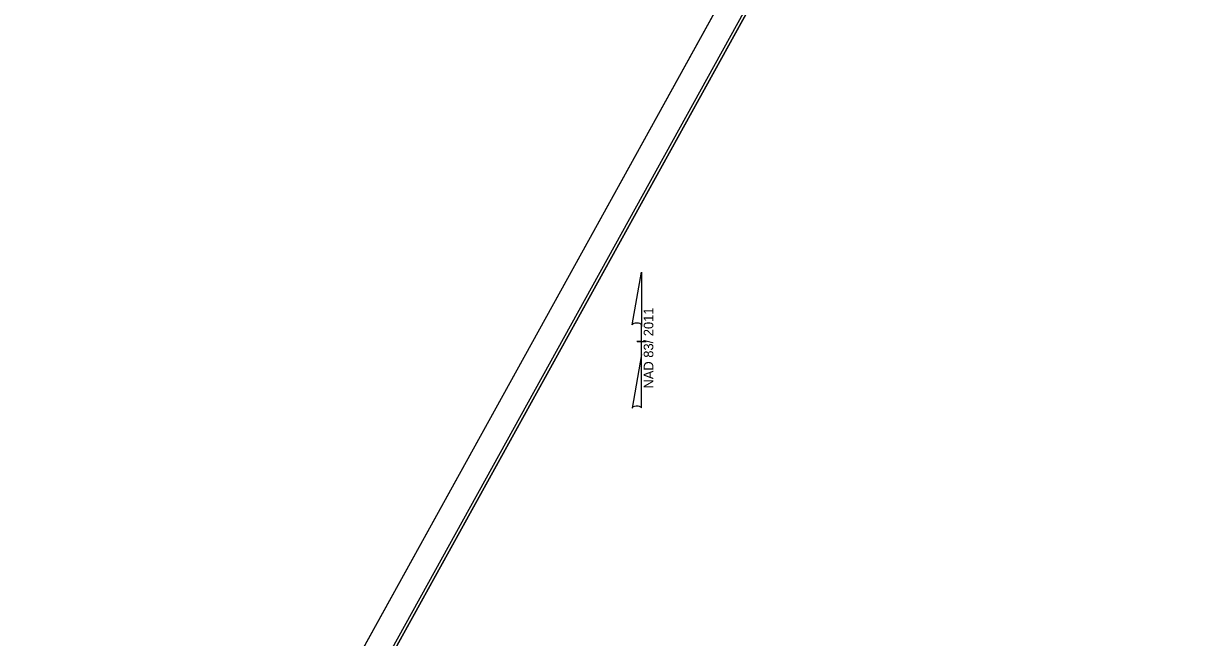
# Model space of a CAD drawing. Extents: x 2176096 to 2177873, y 76962 to 79129.
# Drawn here: x 2176096 to 2177127, y 78046 to 78587 of the extents above; entities that cross this region are included whole.
import ezdxf

# ---------------------------------------------------------------- set-up
doc = ezdxf.new("R2010")
doc.units = 0
for name, color, linetype in [('CTL Primary Horizontal and Vertical CELL', 7, 'Continuous'), ('CTL Primary Horizontal CELL', 7, 'Continuous'), ('CTL Primary Horizontal Cogo Elevation', 7, 'Continuous'), ('CTL Primary Horizontal Cogo Number', 7, 'Continuous'), ('Exist Other Culture Sign Cogo Point CELL', 7, 'Continuous'), ('Exist Property Iron Pin Cogo Comment', 7, 'Continuous')]:
    doc.layers.add(name, color=color, linetype=linetype)

msp = doc.modelspace()

# ---------------------------------------------------------------- linework, layer by layer
at = {"layer": 'CTL Primary Horizontal and Vertical CELL'}
msp.add_lwpolyline([(2176762, 78648.7), (2176276.9, 77771), (2176400.5, 77667.3), (2176500.7, 77583.3), (2176559.2, 77534.4), (2176927.7, 77225.4), (2177117.2, 77120.7), (2177568.3, 77937), (2177830.4, 78411.2), (2177842.7, 78433.6), (2177075.6, 78857.5), (2176978.9, 78682.4), (2176907.9, 78721.6), (2176842.9, 78604)], close=True, dxfattribs=at)
at = {"layer": 'CTL Primary Horizontal CELL'}
msp.add_lwpolyline([(2176927.6, 78953.6), (2176121.5, 77495), (2177045, 76984.7), (2177851, 78443.3)], close=True, dxfattribs=at)
at = {"layer": 'CTL Primary Horizontal Cogo Elevation'}
msp.add_line((2176910.1, 78968.4), (2176095.6, 77494.5), dxfattribs=at)
at = {"layer": 'CTL Primary Horizontal Cogo Number'}
msp.add_lwpolyline([(2176910.1, 78968.4), (2176095.6, 77494.5), (2177058.3, 76962.4), (2177872.8, 78436.3)], close=True, dxfattribs=at)
at = {"layer": 'Exist Other Culture Sign Cogo Point CELL'}
msp.add_lwpolyline([(2176923.7, 78941.4), (2176198.2, 77628.6), (2177117.2, 77120.7), (2177842.7, 78433.6)], close=True, dxfattribs=at)
at = {"layer": 'Exist Property Iron Pin Cogo Comment'}
for p, q in [((2176632.4, 78321.6), (2176640.6, 78367.9)), ((2176640.6, 78367.9), (2176640.6, 78367.9)), ((2176640.6, 78367.9), (2176640.6, 78367.9)), ((2176640.6, 78367.9), (2176640.6, 78320.1)), ((2176640.6, 78295.3), (2176640.6, 78321.5)), ((2176640.6, 78320.1), (2176640.6, 78321.5)), ((2176640.2, 78306.9), (2176636.6, 78306.9)), ((2176636.6, 78306.9), (2176636.6, 78306.9)), ((2176636.7, 78306.9), (2176644.7, 78306.9)), ((2176640.6, 78295.3), (2176632.3, 78248.1)), ((2176640.7, 78248.3), (2176640.6, 78295.3))]:
    msp.add_line(p, q, dxfattribs=at)
for centre, start_param, end_param in [((2176636.5, 78321.1), 0.216388, 2.908219), ((2176636.5, 78247.9), 0.201328, 3.141593)]:
    msp.add_ellipse(centre, major_axis=(4.23, -0.03), ratio=0.461098, start_param=start_param, end_param=end_param, dxfattribs=at)

# ---------------------------------------------------------------- texts
msp.add_text('NAD 83/ 2011', height=8.5, rotation=90, dxfattribs=at).set_placement((2176651.1, 78265.4))

doc.saveas('drawing.dxf')
